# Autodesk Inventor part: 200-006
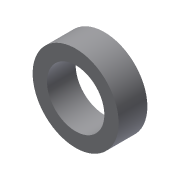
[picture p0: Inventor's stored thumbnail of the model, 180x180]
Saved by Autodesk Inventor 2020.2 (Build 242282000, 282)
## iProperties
Created: 2014-01
Part Number: 200-006
Material: Ogólny
Document SubType Name: Modeling
Designer: F.Stasiak
Density: 1 g/cm^3
Appearance: Domyślna
Manager: www.cadconsulting.pl
Company: Fabian Stasiak CAD Consulting
Author: F.Stasiak
Subject: Zbiór ćwiczeń. Autodesk Inventor 2020. Kurs podstawowy
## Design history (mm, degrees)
sketch "Szkic1"
  geometry: C1 r 15 at (0, 0); C2 r 10 at (0, 0); 1 further point
  constraints: 2 centre point, 2 coincident
  dimensions: "d0" = 30 diameter of C1; "d1" = 20 diameter of C2
extrude "Wyciągnięcie proste1" new body sketch "Szkic1" distance "d2" = 10; taper "d3" = 0 deg
node "Bryła1"
